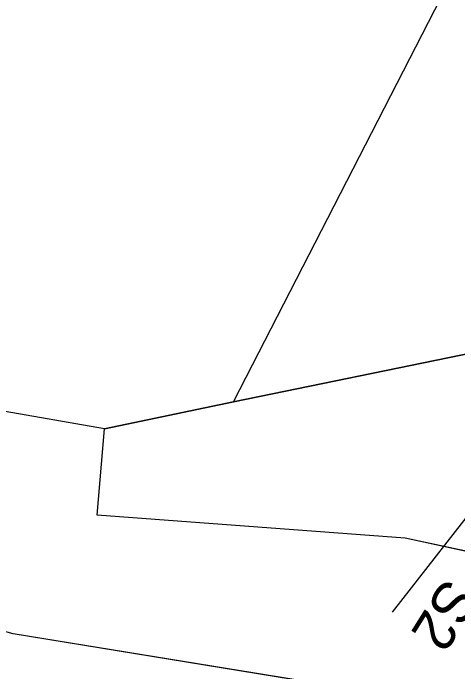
# Model space of a CAD drawing. Extents: x -746176 to -739709, y -1128407 to -1124482.
# Drawn here: x -743181.19 to -743175.78, y -1127095.1 to -1127087.08 of the extents above; entities that cross this region are included whole.
import ezdxf

# ---------------------------------------------------------------- set-up
doc = ezdxf.new("R2010")
doc.units = 0
for name, color, linetype in [('Hranice parcel', 7, 'Continuous'), ('KOMUNIKACE_KRAJNICE', 7, 'Continuous'), ('SRAFA_UPRAVA', 7, 'Continuous'), ('SVAH', 7, 'Continuous'), ('TRATIVOD', 7, 'Continuous'), ('Vrstva 53', 7, 'Continuous')]:
    doc.layers.add(name, color=color, linetype=linetype)

msp = doc.modelspace()

# ---------------------------------------------------------------- linework, layer by layer
at = {"layer": 'Hranice parcel'}
for p, q in [((-743180.08, -1127092.14), (-743206.78, -1127087.5)), ((-743178.51, -1127091.81), (-743180.08, -1127092.14))]:
    msp.add_line(p, q, dxfattribs=at)
for points in [[(-743178.51, -1127091.81), (-743158.66, -1127053.1), (-743097.21, -1126928.95)], [(-743080.97, -1126930.41), (-743108.67, -1126985.4), (-743124.8, -1127012.28), (-743175.35, -1127091.16), (-743178.51, -1127091.81)], [(-743159.64, -1127094.74), (-743160.17, -1127095.91), (-743166.78, -1127095.57), (-743176.42, -1127093.47), (-743180.17, -1127093.19), (-743180.08, -1127092.14)]]:
    msp.add_lwpolyline(points, dxfattribs=at)
at = {"layer": 'KOMUNIKACE_KRAJNICE'}
msp.add_lwpolyline([(-743175.8563, -1127095.5049), (-743181.1912, -1127094.6362)], dxfattribs=at)
at = {"layer": 'SRAFA_UPRAVA'}
for p, q in [((-743181.1912, -1127094.6362), (-743182.1587, -1127094.3756)), ((-743175.8563, -1127095.5049), (-743181.1912, -1127094.6362))]:
    msp.add_line(p, q, dxfattribs=at)
at = {"layer": 'SVAH'}
msp.add_lwpolyline([(-743172.839, -1127089.738), (-743173.7096, -1127090.2683), (-743175.408, -1127092.8684), (-743176.5817, -1127094.3736)], dxfattribs=at)
at = {"layer": 'Vrstva 53'}
msp.add_lwpolyline([(-743032.8, -1126884.17), (-743063.8, -1126932.98), (-743082.27, -1126962.07), (-743093.1, -1126978.92), (-743136.47, -1127047.12), (-743147.78, -1127068.8), (-743159.64, -1127094.74), (-743160.17, -1127095.91), (-743166.78, -1127095.57), (-743176.42, -1127093.47), (-743180.17, -1127093.19), (-743180.08, -1127092.14), (-743178.51, -1127091.81), (-743175.35, -1127091.16), (-743150.075, -1127051.72), (-743124.8, -1127012.28), (-743108.67, -1126985.4), (-743080.97, -1126930.41), (-743079.79, -1126928.05), (-743048.51, -1126865.51), (-743045.12, -1126860.39), (-743029.24, -1126857.99)], dxfattribs=at)

# ---------------------------------------------------------------- texts
at = {"layer": 'TRATIVOD'}
msp.add_text('Š2', height=0.5, rotation=238, dxfattribs=at).set_placement((-743175.9303, -1127093.9324))

doc.saveas('drawing.dxf')
